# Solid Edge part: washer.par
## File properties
Author: Deepak Maini
Template: Normal.par
Last saved by: Robert a Rhodes jr
Revision: 2
Application: Solid Edge
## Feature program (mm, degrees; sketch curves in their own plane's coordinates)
sketch for "unnamed Protrusion 1" #1 plane through (0, 0, 0) normal (0, -1, 0) x-axis (1, 0, 0)
  circle centre (0, 0) radius 16.5
sketch for "unnamed Protrusion 1" #2 plane through (0, 0, 0) normal (0, -1, 0) x-axis (1, 0, 0)
  circle centre (0, 0) radius 31.5
extrude "unnamed Protrusion 1" add finite 10 along +normal
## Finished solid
Body 1: solid body, 4 faces, 4 edges, 0 vertices.
  Faces by surface: cylinder 2, plane 2
  Edges by curve: circle 4
Bounding box of the edges (mm): 63.000 x 10.000 x 63.000, from (-31.5, -10, -31.5) to (31.5, 0, 31.5).
Cylindrical faces by radius (mm): R16.5 x1, R31.5 x1
Planar faces by outward normal: +y 1, -y 1
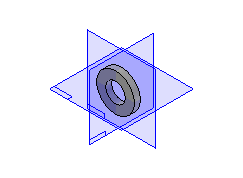
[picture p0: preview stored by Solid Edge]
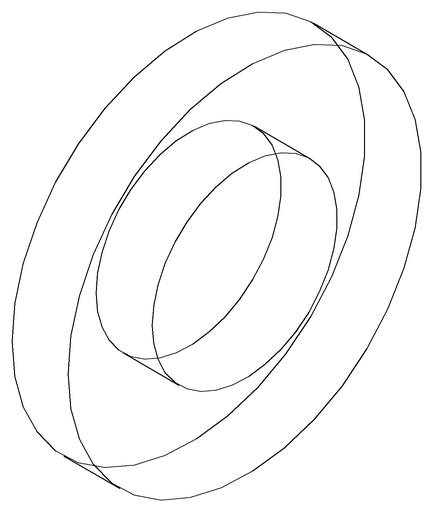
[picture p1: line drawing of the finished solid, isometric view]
